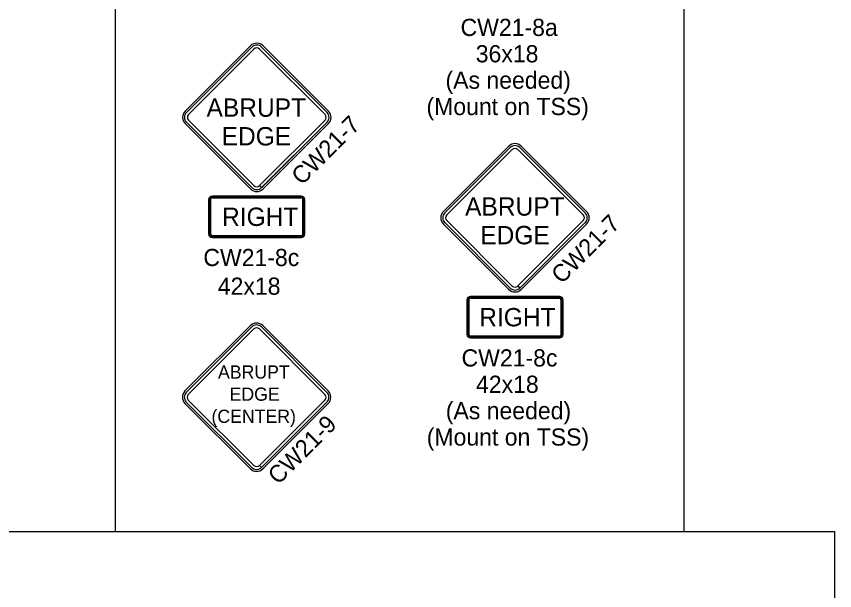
# Model space of a CAD drawing. Extents: x 1458 to 4498, y 17709 to 24109.
# Drawn here: x 2865 to 3578, y 23102 to 23603 of the extents above; entities that cross this region are included whole.
import ezdxf

# ---------------------------------------------------------------- set-up
doc = ezdxf.new("R2010")
doc.units = 0
doc.layers.add('P_ODOT_PLAN_TBlock', color=7, linetype='Continuous')
doc.layers.add('P_TRAF_TCP_General', color=7, linetype='Continuous')

msp = doc.modelspace()

# ---------------------------------------------------------------- linework, layer by layer
at = {"layer": 'P_ODOT_PLAN_TBlock'}
for p, q in [((2951.57, 24109.14), (2951.57, 23153.55)), ((3446.99, 24109.14), (3446.99, 23153.55)), ((1458.44, 23153.55), (3578.44, 23153.55)), ((3578.44, 23153.55), (3578.44, 22109.14))]:
    msp.add_line(p, q, dxfattribs=at)
at = {"layer": 'P_TRAF_TCP_General'}
for p, q in [((3069.44, 23577.08), (3012.43, 23520.08)), ((3070.62, 23575.9), (3013.61, 23518.89)), ((3070.62, 23575.9), (3013.61, 23518.89)), ((3070.62, 23575.9), (3013.61, 23518.89)), ((3136.11, 23518.89), (3079.1, 23575.9)), ((3136.11, 23518.89), (3079.1, 23575.9)), ((3136.11, 23518.89), (3079.1, 23575.9)), ((3137.29, 23520.08), (3080.29, 23577.08)), ((3015.38, 23517.13), (3072.39, 23574.13)), ((3015.38, 23517.13), (3072.39, 23574.13)), ((3077.33, 23574.13), (3134.34, 23517.13)), ((3077.33, 23574.13), (3134.34, 23517.13)), ((3072.39, 23455.17), (3015.38, 23512.18)), ((3072.39, 23455.17), (3015.38, 23512.18)), ((3134.34, 23512.18), (3077.35, 23455.19)), ((3134.34, 23512.18), (3077.35, 23455.19)), ((3012.43, 23509.23), (3069.44, 23452.22)), ((3013.61, 23510.41), (3070.62, 23453.41)), ((3013.61, 23510.41), (3070.62, 23453.41)), ((3013.61, 23510.41), (3070.62, 23453.41)), ((3079.1, 23453.41), (3136.11, 23510.41)), ((3079.12, 23453.43), (3136.11, 23510.41)), ((3079.12, 23453.43), (3136.11, 23510.41)), ((3080.29, 23452.22), (3137.29, 23509.23)), ((3294.46, 23489.53), (3237.46, 23432.52)), ((3362.32, 23432.52), (3305.31, 23489.53)), ((3295.65, 23488.34), (3238.64, 23431.34)), ((3295.65, 23488.34), (3238.64, 23431.34)), ((3295.65, 23488.34), (3238.64, 23431.34)), ((3240.41, 23429.57), (3297.41, 23486.58)), ((3240.41, 23429.57), (3297.41, 23486.58)), ((3302.36, 23486.58), (3359.37, 23429.57)), ((3302.36, 23486.58), (3359.37, 23429.57)), ((3361.13, 23431.34), (3304.13, 23488.34)), ((3361.13, 23431.34), (3304.13, 23488.34)), ((3361.13, 23431.34), (3304.13, 23488.34)), ((3079.1, 23453.41), (3077.33, 23455.17)), ((3079.1, 23453.41), (3077.33, 23455.17)), ((3077.35, 23455.19), (3079.12, 23453.43)), ((3077.35, 23455.19), (3079.12, 23453.43)), ((3032.88, 23443.17), (3032.88, 23412.8)), ((3033.53, 23443.17), (3033.53, 23412.8)), ((3033.53, 23443.17), (3033.53, 23412.8)), ((3034.63, 23443.17), (3034.63, 23412.8)), ((3034.63, 23412.8), (3034.63, 23443.17)), ((3113.56, 23445.98), (3036.16, 23445.98)), ((3113.56, 23445.42), (3036.16, 23445.42)), ((3113.56, 23445.42), (3036.16, 23445.42)), ((3113.56, 23444.48), (3036.16, 23444.48)), ((3036.16, 23444.48), (3113.56, 23444.48)), ((3115.09, 23412.8), (3115.09, 23443.17)), ((3115.09, 23443.17), (3115.09, 23412.8)), ((3116.19, 23412.8), (3116.19, 23443.17)), ((3116.19, 23412.8), (3116.19, 23443.17)), ((3116.84, 23412.8), (3116.84, 23443.17)), ((3237.46, 23421.67), (3294.46, 23364.67)), ((3238.64, 23422.86), (3295.65, 23365.85)), ((3238.64, 23422.86), (3295.65, 23365.85)), ((3238.64, 23422.86), (3295.65, 23365.85)), ((3297.41, 23367.62), (3240.41, 23424.62)), ((3297.41, 23367.62), (3240.41, 23424.62)), ((3359.37, 23424.62), (3302.38, 23367.64)), ((3359.37, 23424.62), (3302.38, 23367.64)), ((3304.13, 23365.85), (3361.13, 23422.86)), ((3304.15, 23365.87), (3361.13, 23422.86)), ((3304.15, 23365.87), (3361.13, 23422.86)), ((3305.31, 23364.67), (3362.32, 23421.67)), ((3036.16, 23411.49), (3113.56, 23411.49)), ((3036.16, 23410.55), (3036.16, 23411.49)), ((3113.56, 23411.49), (3036.17, 23411.49)), ((3036.17, 23411.49), (3036.17, 23410.55)), ((3036.16, 23410.55), (3113.56, 23410.55)), ((3036.16, 23409.99), (3113.56, 23409.99)), ((3036.17, 23410.55), (3113.56, 23410.55)), ((3304.13, 23365.85), (3302.36, 23367.62)), ((3304.13, 23365.85), (3302.36, 23367.62)), ((3302.38, 23367.64), (3304.15, 23365.87)), ((3302.38, 23367.64), (3304.15, 23365.87)), ((3257.9, 23355.61), (3257.9, 23325.25)), ((3258.56, 23355.61), (3258.56, 23325.25)), ((3258.56, 23355.61), (3258.56, 23325.25)), ((3259.65, 23355.61), (3259.65, 23325.25)), ((3259.65, 23325.25), (3259.65, 23355.61)), ((3338.59, 23358.42), (3261.18, 23358.42)), ((3338.59, 23357.86), (3261.18, 23357.86)), ((3338.59, 23357.86), (3261.18, 23357.86)), ((3338.59, 23356.92), (3261.18, 23356.92)), ((3261.18, 23356.92), (3338.59, 23356.92)), ((3340.12, 23325.25), (3340.12, 23355.61)), ((3340.12, 23355.61), (3340.12, 23325.25)), ((3341.21, 23325.25), (3341.21, 23355.61)), ((3341.21, 23325.25), (3341.21, 23355.61)), ((3341.87, 23325.25), (3341.87, 23355.61)), ((3069.25, 23333.1), (3012.24, 23276.09)), ((3137.1, 23276.09), (3080.1, 23333.1)), ((3070.43, 23331.91), (3013.43, 23274.91)), ((3070.43, 23331.91), (3013.43, 23274.91)), ((3070.43, 23331.91), (3013.43, 23274.91)), ((3015.2, 23273.14), (3072.2, 23330.15)), ((3015.2, 23273.14), (3072.2, 23330.15)), ((3077.15, 23330.15), (3134.15, 23273.14)), ((3077.15, 23330.15), (3134.15, 23273.14)), ((3135.92, 23274.91), (3078.92, 23331.91)), ((3135.92, 23274.91), (3078.92, 23331.91)), ((3135.92, 23274.91), (3078.92, 23331.91)), ((3261.18, 23323.94), (3338.59, 23323.94)), ((3261.18, 23323), (3261.18, 23323.94)), ((3261.18, 23323), (3338.59, 23323)), ((3261.18, 23322.44), (3338.59, 23322.44)), ((3338.59, 23323.94), (3261.19, 23323.94)), ((3261.19, 23323.94), (3261.19, 23323)), ((3261.19, 23323), (3338.59, 23323)), ((3012.24, 23265.24), (3069.25, 23208.24)), ((3013.43, 23266.43), (3070.43, 23209.42)), ((3013.43, 23266.43), (3070.43, 23209.42)), ((3013.43, 23266.43), (3070.43, 23209.42)), ((3072.2, 23211.19), (3015.2, 23268.19)), ((3072.2, 23211.19), (3015.2, 23268.19)), ((3134.15, 23268.19), (3077.17, 23211.21)), ((3134.15, 23268.19), (3077.17, 23211.21)), ((3078.92, 23209.42), (3135.92, 23266.43)), ((3078.93, 23209.44), (3135.92, 23266.43)), ((3078.93, 23209.44), (3135.92, 23266.43)), ((3080.1, 23208.24), (3137.1, 23265.24)), ((3078.92, 23209.42), (3077.15, 23211.19)), ((3078.92, 23209.42), (3077.15, 23211.19)), ((3077.17, 23211.21), (3078.93, 23209.44)), ((3077.17, 23211.21), (3078.93, 23209.44))]:
    msp.add_line(p, q, dxfattribs=at)
for centre, radius, start, end in [((3074.86, 23571.66), 7.67, 45, 135), ((3074.86, 23571.66), 6, 45, 135), ((3074.86, 23571.66), 6, 45, 135), ((3074.86, 23571.66), 6, 45, 135), ((3074.86, 23571.66), 3.5, 45, 135), ((3074.86, 23571.66), 3.5, 45, 135), ((3017.86, 23514.65), 7.67, 135, 225), ((3017.86, 23514.65), 6, 135, 225), ((3017.86, 23514.65), 6, 135, 225), ((3017.86, 23514.65), 6, 135, 225), ((3131.87, 23514.65), 6, 315, 45), ((3131.87, 23514.65), 6, 315, 45), ((3131.87, 23514.65), 6, 315, 45), ((3131.87, 23514.65), 7.67, 315, 45), ((3017.86, 23514.65), 3.5, 135, 225), ((3017.86, 23514.65), 3.5, 135, 225), ((3131.87, 23514.65), 3.5, 315, 45), ((3131.87, 23514.65), 3.5, 315, 45), ((3299.89, 23484.1), 7.67, 45, 135), ((3299.89, 23484.1), 6, 45, 135), ((3299.89, 23484.1), 6, 45, 135), ((3299.89, 23484.1), 6, 45, 135), ((3299.89, 23484.1), 3.5, 45, 135), ((3299.89, 23484.1), 3.5, 45, 135), ((3074.86, 23457.65), 3.5, 225, 315), ((3074.86, 23457.65), 3.5, 225, 315), ((3074.86, 23457.65), 7.67, 225, 315), ((3074.86, 23457.65), 6, 225, 315), ((3074.86, 23457.65), 6, 225, 315), ((3074.86, 23457.65), 6, 225, 315), ((3242.88, 23427.1), 7.67, 135, 225), ((3356.89, 23427.1), 7.67, 315, 45), ((3242.88, 23427.1), 6, 135, 225), ((3242.88, 23427.1), 6, 135, 225), ((3242.88, 23427.1), 6, 135, 225), ((3242.88, 23427.1), 3.5, 135, 225), ((3242.88, 23427.1), 3.5, 135, 225), ((3356.89, 23427.1), 3.5, 315, 45), ((3356.89, 23427.1), 3.5, 315, 45), ((3356.89, 23427.1), 6, 315, 45), ((3356.89, 23427.1), 6, 315, 45), ((3356.89, 23427.1), 6, 315, 45), ((3299.89, 23370.09), 7.67, 225, 315), ((3299.89, 23370.09), 6, 225, 315), ((3299.89, 23370.09), 6, 225, 315), ((3299.89, 23370.09), 6, 225, 315), ((3299.89, 23370.09), 3.5, 225, 315), ((3299.89, 23370.09), 3.5, 225, 315), ((3074.67, 23327.67), 7.67, 45, 135), ((3074.67, 23327.67), 6, 45, 135), ((3074.67, 23327.67), 6, 45, 135), ((3074.67, 23327.67), 6, 45, 135), ((3074.67, 23327.67), 3.5, 45, 135), ((3074.67, 23327.67), 3.5, 45, 135), ((3017.67, 23270.67), 7.67, 135, 225), ((3131.68, 23270.67), 7.67, 315, 45), ((3017.67, 23270.67), 6, 135, 225), ((3017.67, 23270.67), 6, 135, 225), ((3017.67, 23270.67), 6, 135, 225), ((3017.67, 23270.67), 3.5, 135, 225), ((3017.67, 23270.67), 3.5, 135, 225), ((3131.68, 23270.67), 3.5, 315, 45), ((3131.68, 23270.67), 3.5, 315, 45), ((3131.68, 23270.67), 6, 315, 45), ((3131.68, 23270.67), 6, 315, 45), ((3131.68, 23270.67), 6, 315, 45), ((3074.67, 23213.66), 7.67, 225, 315), ((3074.67, 23213.66), 6, 225, 315), ((3074.67, 23213.66), 6, 225, 315), ((3074.67, 23213.66), 6, 225, 315), ((3074.67, 23213.66), 3.5, 225, 315), ((3074.67, 23213.66), 3.5, 225, 315)]:
    msp.add_arc(centre, radius, start, end, dxfattribs=at)
for centre, major_axis, start_param, end_param in [((3036.16, 23443.17), (3.28, 0), 1.570796, 3.141593), ((3036.16, 23443.17), (2.62, 0), 1.570796, 3.141593), ((3036.16, 23443.17), (2.62, 0), 1.570796, 3.141593), ((3036.16, 23443.17), (1.53, 0), 1.570796, 3.141593), ((3036.16, 23443.17), (1.53, 0), 1.570796, 3.141593), ((3113.56, 23443.17), (3.28, 0), 0, 1.570796), ((3113.56, 23443.17), (2.62, 0), 0, 1.570796), ((3113.56, 23443.17), (2.62, 0), 0, 1.570796), ((3113.56, 23443.17), (1.53, 0), 0, 1.570796), ((3113.56, 23443.17), (1.53, 0), 0, 1.570796), ((3036.16, 23412.8), (3.28, 0), 3.141593, 4.712389), ((3036.16, 23412.8), (2.62, 0), 3.141593, 4.712389), ((3036.16, 23412.8), (2.62, 0), 3.141593, 4.712389), ((3036.16, 23412.8), (1.53, 0), 3.141593, 4.712389), ((3036.16, 23412.8), (1.53, 0), 3.141593, 4.712389), ((3113.56, 23412.8), (2.62, 0), 4.712389, 6.283185), ((3113.56, 23412.8), (1.53, 0), 4.712389, 6.283185), ((3113.56, 23412.8), (2.62, 0), 4.712389, 6.283185), ((3113.56, 23412.8), (1.53, 0), 4.712389, 6.283185), ((3113.56, 23412.8), (3.28, 0), 4.712389, 6.283185), ((3261.18, 23355.61), (3.28, 0), 1.570796, 3.141593), ((3261.18, 23355.61), (2.62, 0), 1.570796, 3.141593), ((3261.18, 23355.61), (2.62, 0), 1.570796, 3.141593), ((3261.18, 23355.61), (1.53, 0), 1.570796, 3.141593), ((3261.18, 23355.61), (1.53, 0), 1.570796, 3.141593), ((3338.59, 23355.61), (3.28, 0), 0, 1.570796), ((3338.59, 23355.61), (2.62, 0), 0, 1.570796), ((3338.59, 23355.61), (2.62, 0), 0, 1.570796), ((3338.59, 23355.61), (1.53, 0), 0, 1.570796), ((3338.59, 23355.61), (1.53, 0), 0, 1.570796), ((3261.18, 23325.25), (3.28, 0), 3.141593, 4.712389), ((3261.18, 23325.25), (2.62, 0), 3.141593, 4.712389), ((3261.18, 23325.25), (2.62, 0), 3.141593, 4.712389), ((3261.18, 23325.25), (1.53, 0), 3.141593, 4.712389), ((3261.18, 23325.25), (1.53, 0), 3.141593, 4.712389), ((3338.59, 23325.25), (2.62, 0), 4.712389, 6.283185), ((3338.59, 23325.25), (1.53, 0), 4.712389, 6.283185), ((3338.59, 23325.25), (2.62, 0), 4.712389, 6.283185), ((3338.59, 23325.25), (1.53, 0), 4.712389, 6.283185), ((3338.59, 23325.25), (3.28, 0), 4.712389, 6.283185)]:
    msp.add_ellipse(centre, major_axis=major_axis, ratio=0.857143, start_param=start_param, end_param=end_param, dxfattribs=at)

# ---------------------------------------------------------------- texts
for s, height, p in [('CW21-8a', 14.994, (3252.44, 23585.64)), ('36x18', 14.994, (3265.69, 23562.65)), ('(As needed)', 14.994, (3239.35, 23539.66)), ('(Mount on TSS)', 14.994, (3222.75, 23516.66)), ('ABRUPT', 15.994, (3031.06, 23515.19)), ('EDGE', 15.994, (3044.21, 23490.2)), ('ABRUPT', 15.994, (3256.41, 23428.99)), ('RIGHT', 15.994, (3044.59, 23420)), ('EDGE', 15.994, (3269.57, 23404)), ('CW21-8c', 14.994, (3028.3, 23385)), ('42x18', 14.994, (3040.89, 23360.01)), ('RIGHT', 15.994, (3268.71, 23332.44)), ('CW21-8c', 14.994, (3253.32, 23297.45)), ('ABRUPT', 11.52, (3041.05, 23286.88)), ('42x18', 14.994, (3265.91, 23274.45)), ('EDGE', 11.52, (3051.16, 23267.57)), ('(As needed)', 14.994, (3239.58, 23251.46)), ('(CENTER)', 11.52, (3035.38, 23248.26)), ('(Mount on TSS)', 14.994, (3222.97, 23228.47))]:
    msp.add_text(s, height=height, dxfattribs=at).set_placement(p)
for s, p in [('CW21-7', (3114.1, 23454.84)), ('CW21-7', (3340.57, 23368.72)), ('CW21-9', (3093.57, 23193.68))]:
    msp.add_text(s, height=14.994, rotation=45, dxfattribs=at).set_placement(p)

doc.saveas('drawing.dxf')
